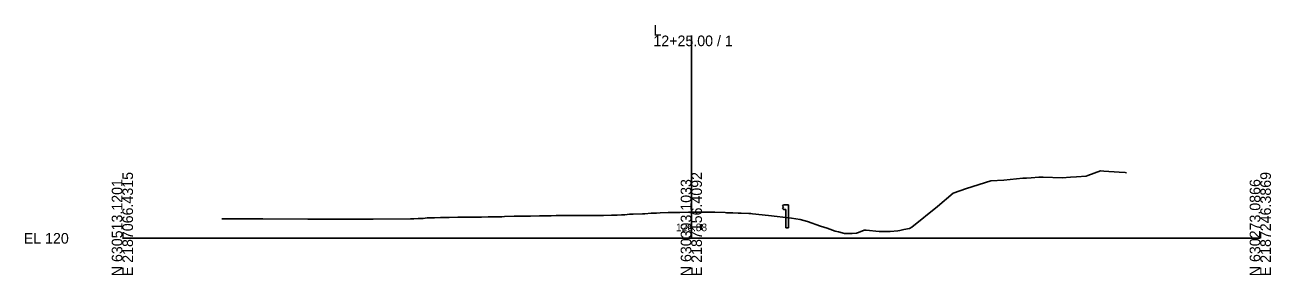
# Model space of a CAD drawing. Extents: x -26 to 4903, y -1010 to 9587.
# Drawn here: x -25.7 to 302.8, y -509.7 to -443.7 of the extents above; entities that cross this region are included whole.
import ezdxf

# ---------------------------------------------------------------- set-up
doc = ezdxf.new("R2010")
doc.units = 0
for name, color, linetype in [('Default', 7, 'Continuous'), ('Exist Cross Section Cell', 7, 'Continuous'), ('Exist XS Center Line Elevation Label', 7, 'Continuous'), ('Exist XS Ground Line', 7, 'Continuous'), ('Prop CMT Guardrail Graphics', 7, 'Continuous')]:
    doc.layers.add(name, color=color, linetype=linetype)

msp = doc.modelspace()

# ---------------------------------------------------------------- linework, layer by layer
at = {"layer": 'Exist Cross Section Cell'}
for p, q in [((150, -500), (150, -446.55)), ((0, -500), (150, -500)), ((150, -500), (300, -500))]:
    msp.add_line(p, q, dxfattribs=at)
at = {"layer": 'Exist XS Ground Line'}
for p, q in [((254.56, -483.43), (257.9, -482.18)), ((257.9, -482.18), (258.73, -482.27)), ((258.73, -482.27), (262.83, -482.56)), ((262.83, -482.56), (264.39, -482.67)), ((264.39, -482.67), (264.71, -482.7)), ((222.5, -486.86), (228.98, -484.82)), ((228.98, -484.82), (232.42, -484.64)), ((232.42, -484.64), (237.37, -484.11)), ((237.37, -484.11), (238.38, -484.19)), ((238.38, -484.19), (239.56, -484.09)), ((239.56, -484.09), (241.65, -483.9)), ((241.65, -483.9), (242.73, -483.86)), ((242.73, -483.86), (247.8, -484.04)), ((247.8, -484.04), (249.96, -483.86)), ((249.96, -483.86), (251.57, -483.76)), ((251.57, -483.76), (254.09, -483.61)), ((254.09, -483.61), (254.56, -483.43)), ((214.91, -491.65), (219.06, -488.12)), ((219.06, -488.12), (222.5, -486.86)), ((208.09, -497.07), (214.91, -491.65)), ((26.18, -494.88), (32.51, -494.88)), ((32.51, -494.88), (33.47, -494.87)), ((33.47, -494.87), (37.01, -494.87)), ((37.01, -494.87), (48.93, -494.96)), ((48.93, -494.96), (49.82, -494.95)), ((49.82, -494.95), (50.6, -494.95)), ((50.6, -494.95), (52.63, -494.96)), ((52.63, -494.96), (54.23, -494.98)), ((54.23, -494.98), (56.52, -494.95)), ((56.52, -494.95), (63.17, -494.95)), ((63.17, -494.95), (65.08, -494.95)), ((65.08, -494.95), (66.16, -494.95)), ((66.16, -494.95), (75.98, -494.9)), ((75.98, -494.9), (76.81, -494.87)), ((76.81, -494.87), (77.96, -494.8)), ((77.96, -494.8), (79.26, -494.78)), ((79.26, -494.78), (80.31, -494.62)), ((80.31, -494.62), (81.89, -494.6)), ((81.89, -494.6), (82.26, -494.59)), ((82.26, -494.59), (83.9, -494.55)), ((83.9, -494.55), (85.34, -494.51)), ((85.34, -494.51), (85.69, -494.51)), ((85.69, -494.51), (86.17, -494.5)), ((86.17, -494.5), (88.42, -494.46)), ((88.42, -494.46), (89.27, -494.45)), ((89.27, -494.45), (90.44, -494.43)), ((90.44, -494.43), (91.06, -494.42)), ((91.06, -494.42), (91.5, -494.41)), ((91.5, -494.41), (94.23, -494.41)), ((94.23, -494.41), (94.72, -494.41)), ((94.72, -494.41), (96.43, -494.37)), ((96.43, -494.37), (97.66, -494.33)), ((97.66, -494.33), (99, -494.31)), ((99, -494.31), (100.01, -494.3)), ((100.01, -494.3), (100.75, -494.28)), ((100.75, -494.28), (103.28, -494.2)), ((103.28, -494.2), (103.83, -494.19)), ((103.83, -494.19), (105.39, -494.17)), ((105.39, -494.17), (106.91, -494.14)), ((106.91, -494.14), (107.56, -494.13)), ((107.56, -494.13), (109.99, -494.09)), ((109.99, -494.09), (110.76, -494.09)), ((110.76, -494.09), (111.83, -494.08)), ((111.83, -494.08), (113.07, -494.06)), ((113.07, -494.06), (114.34, -494.03)), ((114.34, -494.03), (116.15, -494)), ((116.15, -494), (117.92, -493.99)), ((117.92, -493.99), (119.23, -493.97)), ((119.23, -493.97), (119.72, -493.97)), ((119.72, -493.97), (120.39, -493.97)), ((120.39, -493.97), (121.51, -493.96)), ((121.51, -493.96), (122.31, -493.96)), ((122.31, -493.96), (124.67, -493.95)), ((124.67, -493.95), (125.39, -493.95)), ((125.39, -493.95), (126.88, -493.95)), ((126.88, -493.95), (128.95, -493.92)), ((128.95, -493.92), (130.46, -493.89)), ((130.46, -493.89), (131.55, -493.85)), ((131.55, -493.85), (132.48, -493.8)), ((132.48, -493.8), (133.66, -493.68)), ((133.66, -493.68), (134.07, -493.67)), ((134.07, -493.67), (134.7, -493.63)), ((134.7, -493.63), (137.16, -493.53)), ((137.16, -493.53), (137.71, -493.51)), ((137.71, -493.51), (139.42, -493.41)), ((139.42, -493.41), (140.8, -493.35)), ((140.8, -493.35), (141.78, -493.31)), ((141.78, -493.31), (143.88, -493.23)), ((143.88, -493.23), (145.37, -493.18)), ((145.37, -493.18), (146.96, -493.16)), ((146.96, -493.16), (149.27, -493.13)), ((149.27, -493.13), (150.34, -493.12)), ((150.34, -493.12), (151.95, -493.1)), ((151.95, -493.1), (153.12, -493.1)), ((153.12, -493.1), (154.56, -493.1)), ((154.56, -493.1), (155.19, -493.1)), ((155.19, -493.1), (155.71, -493.13)), ((155.71, -493.13), (156.2, -493.15)), ((156.2, -493.15), (158.89, -493.23)), ((158.89, -493.23), (159.28, -493.25)), ((159.28, -493.25), (160.91, -493.31)), ((160.91, -493.31), (162.36, -493.38)), ((162.36, -493.38), (163.17, -493.41)), ((163.17, -493.41), (165.19, -493.48)), ((165.19, -493.48), (165.72, -493.5)), ((165.72, -493.5), (166.15, -493.51)), ((166.15, -493.51), (170.36, -494.01)), ((170.36, -494.01), (176.37, -494.66)), ((176.37, -494.66), (178.73, -495)), ((178.73, -495), (180.64, -495.54)), ((180.64, -495.54), (184.09, -496.82)), ((184.09, -496.82), (185.82, -497.34)), ((185.82, -497.34), (187.95, -498.14)), ((187.95, -498.14), (188.79, -498.29)), ((188.79, -498.29), (190.36, -498.76)), ((190.36, -498.76), (192.41, -498.72)), ((192.41, -498.72), (193.5, -498.62)), ((193.5, -498.62), (194.07, -498.45)), ((194.07, -498.45), (195.52, -497.84)), ((195.52, -497.84), (196.09, -497.82)), ((196.09, -497.82), (199.55, -498.17)), ((199.55, -498.17), (202.43, -498.22)), ((202.43, -498.22), (204.4, -498.04)), ((204.4, -498.04), (204.99, -497.97)), ((204.99, -497.97), (206.05, -497.68)), ((206.05, -497.68), (207.5, -497.45)), ((207.5, -497.45), (208.09, -497.07))]:
    msp.add_line(p, q, dxfattribs=at)
at = {"layer": 'Prop CMT Guardrail Graphics'}
for p, q in [((174.28, -491.22), (174.01, -491.51)), ((174.01, -491.51), (174.28, -491.8)), ((174.28, -491.8), (174.01, -492.1)), ((174.01, -492.1), (174.28, -492.39)), ((175.61, -491.22), (174.28, -491.22)), ((174.28, -492.39), (174.95, -492.39)), ((174.95, -492.39), (174.95, -497.22)), ((175.61, -497.22), (175.61, -491.22)), ((174.95, -497.22), (175.61, -497.22))]:
    msp.add_line(p, q, dxfattribs=at)

# ---------------------------------------------------------------- texts
at = {"layer": 'Default'}
msp.add_text('-', height=0.0001, dxfattribs=at).set_placement((0, -500))
at = {"layer": 'Exist Cross Section Cell'}
for s, p in [('12+25.00 / 1', (140, -449.35)), ('L', (140, -446.55)), ('EL 120', (-26, -501.4))]:
    msp.add_text(s, height=2.8, dxfattribs=at).set_placement(p)
for s, p in [('E 2187066.4315', (2.8, -510)), ('E 2187156.4092', (152.8, -510)), ('E 2187246.3869', (302.8, -510)), ('N 630513.1201', (0, -510)), ('N 630393.1033', (150, -510)), ('N 630273.0866', (300, -510))]:
    msp.add_text(s, height=2.8, rotation=90, dxfattribs=at).set_placement(p)
at = {"layer": 'Exist XS Center Line Elevation Label'}
msp.add_text('126.88', height=2, dxfattribs=at).set_placement((145.96, -498.12))
msp.add_text('126.88', height=2, dxfattribs=at).set_placement((145.96, -498.12))

doc.saveas('drawing.dxf')
